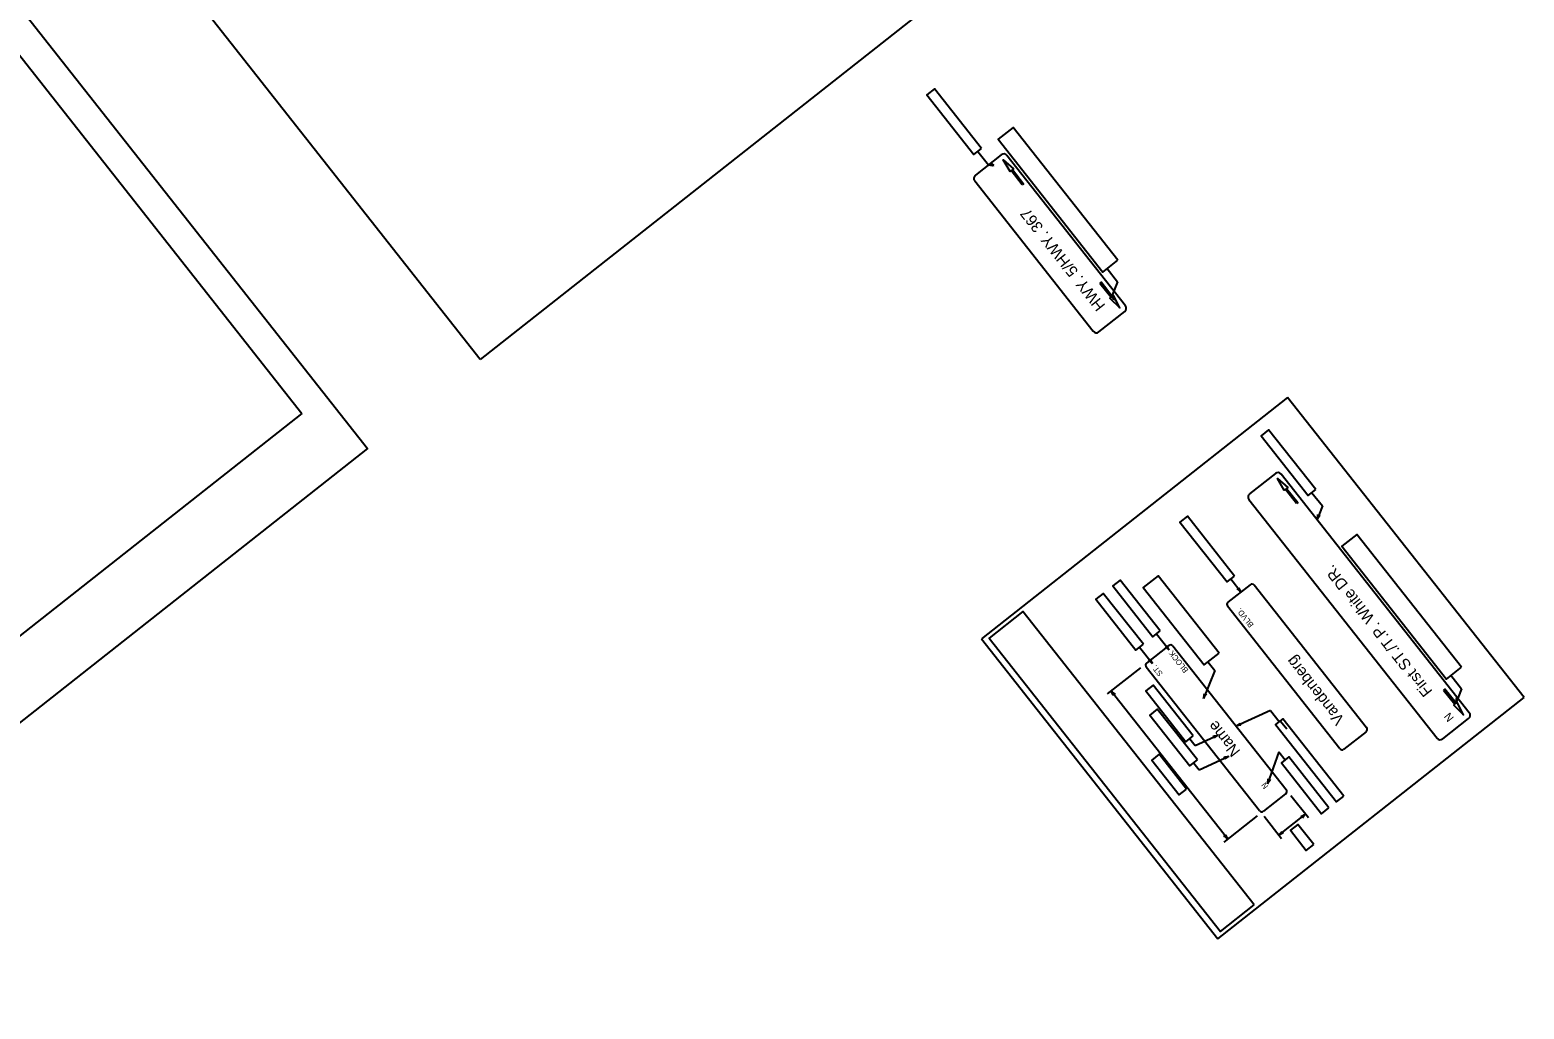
# Model space of a CAD drawing. Extents: x 671946 to 673995, y 1673066 to 1674936.
# Drawn here: x 672850 to 673939, y 1673066 to 1673780 of the extents above; entities that cross this region are included whole.
import ezdxf

# ---------------------------------------------------------------- set-up
doc = ezdxf.new("R2010")
doc.units = 0
for name, color, linetype in [('1', 7, 'Continuous'), ('Default', 7, 'Continuous'), ('G-ANNO-TTLB', 7, 'Continuous'), ('No Plot', 7, 'Continuous'), ('R_No Plot', 7, 'Continuous'), ('T_Drafting', 7, 'Continuous')]:
    doc.layers.add(name, color=color, linetype=linetype)

msp = doc.modelspace()

# ---------------------------------------------------------------- linework, layer by layer
at = {"layer": '1'}
for p, q in [((672460.5, 1674245.5), (673047.7, 1673500.6)), ((673047.7, 1673500.6), (672563.7, 1673119))]:
    msp.add_line(p, q, dxfattribs=at)
at = {"layer": 'Default'}
for points in [[(673543.2, 1673693.5), (673508.8, 1673737.1), (673503.4, 1673732.8), (673537.7, 1673689.2)], [(673642.5, 1673612.2), (673566.2, 1673709), (673555.3, 1673700.4), (673631.6, 1673603.6)], [(673786.8, 1673445), (673752.4, 1673488.6), (673746.9, 1673484.3), (673781.3, 1673440.7)], [(673727.5, 1673382), (673693.2, 1673425.7), (673687.7, 1673421.4), (673722.1, 1673377.8)], [(673893, 1673315.6), (673816.7, 1673412.4), (673805.8, 1673403.8), (673882.1, 1673307)], [(673716.4, 1673325.9), (673671.9, 1673382.3), (673661, 1673373.7), (673705.5, 1673317.3)], [(673673.5, 1673342), (673644.3, 1673379.1), (673638.8, 1673374.8), (673668.1, 1673337.7)], [(673661.2, 1673332.3), (673631.9, 1673369.4), (673626.5, 1673365.1), (673655.7, 1673328)], [(673697.5, 1673265.5), (673668.3, 1673302.6), (673662.9, 1673298.3), (673692.1, 1673261.2)], [(673700.5, 1673248), (673671.3, 1673285), (673665.8, 1673280.7), (673695.1, 1673243.7)], [(673807.3, 1673221.7), (673762.8, 1673278.1), (673757.4, 1673273.8), (673801.9, 1673217.4)], [(673692.6, 1673226.8), (673672.6, 1673252.2), (673667.2, 1673247.9), (673687.2, 1673222.5)], [(673796.4, 1673213.1), (673767.2, 1673250.2), (673761.7, 1673245.9), (673791, 1673208.8)], [(673785.4, 1673186.4), (673773.8, 1673201.1), (673768.3, 1673196.8), (673779.9, 1673182.1)]]:
    msp.add_lwpolyline(points, close=True, dxfattribs=at)
at = {"layer": 'G-ANNO-TTLB'}
msp.add_lwpolyline([(673177.8, 1673539.8), (672546.3, 1674340.9), (673064.6, 1674749.5), (673696.1, 1673948.5)], close=True, dxfattribs=at)
at = {"layer": 'No Plot'}
msp.add_lwpolyline([(673741.9, 1673142.5), (673573.4, 1673356.2), (673548.8, 1673336.8), (673717.3, 1673123.1)], close=True, dxfattribs=at)
at = {"layer": 'R_No Plot'}
msp.add_lwpolyline([(672577.3, 1673066.5), (671945.8, 1673867.5), (672464.1, 1674276.1), (673095.6, 1673475.1)], close=True, dxfattribs=at)
at = {"layer": 'T_Drafting'}
for p, q in [((673557.6, 1673689), (673538.7, 1673674.1)), ((673540.5, 1673691.3), (673548.2, 1673681.6)), ((673648.1, 1673579), (673561.7, 1673688.6)), ((673538.2, 1673670), (673624.6, 1673560.4)), ((673634.7, 1673606.2), (673642.4, 1673596.5)), ((673642.4, 1673596.5), (673638.4, 1673586.6)), ((673628.7, 1673559.9), (673647.6, 1673574.9)), ((673766.2, 1673512.2), (673543.1, 1673336.3)), ((673938.6, 1673293.5), (673766.2, 1673512.2)), ((673757.5, 1673456.8), (673738.5, 1673441.9)), ((673898.7, 1673282.4), (673761.6, 1673456.3)), ((673738.1, 1673437.8), (673875.2, 1673263.9)), ((673784, 1673442.8), (673791.7, 1673433.1)), ((673791.7, 1673433.1), (673787.7, 1673423.2)), ((673739, 1673375.7), (673722.8, 1673363)), ((673724.8, 1673379.9), (673732.3, 1673370.4)), ((673823.8, 1673271.5), (673741.9, 1673375.4)), ((673804.3, 1673256.2), (673722.5, 1673360.1)), ((673670.8, 1673339.9), (673680, 1673328.2)), ((673543.1, 1673336.3), (673715.5, 1673117.6)), ((673658.4, 1673330.1), (673667.7, 1673318.4)), ((673679.7, 1673331.4), (673663.5, 1673318.6)), ((673765.2, 1673226.3), (673682.6, 1673331)), ((673745.8, 1673211), (673663.2, 1673315.7)), ((673708.4, 1673319.4), (673713.3, 1673313.2)), ((673634.9, 1673296.1), (673659.2, 1673315.2)), ((673713.3, 1673313.2), (673705, 1673292.9)), ((673885.3, 1673309.7), (673893, 1673299.9)), ((673722.7, 1673190.2), (673637.6, 1673298.2)), ((673893, 1673299.9), (673889, 1673290)), ((673715.5, 1673117.6), (673938.6, 1673293.5)), ((673753.8, 1673284), (673728.7, 1673272.6)), ((673753.8, 1673284), (673760.1, 1673276)), ((673761.1, 1673276.4), (673765.7, 1673270.6)), ((673879.3, 1673263.4), (673898.2, 1673278.3)), ((673695, 1673263.5), (673698.8, 1673258.6)), ((673698.8, 1673258.6), (673715.5, 1673266.2)), ((673823.4, 1673268.6), (673807.2, 1673255.9)), ((673701.7, 1673240.9), (673723.4, 1673250.8)), ((673759.9, 1673253.9), (673751.7, 1673230.6)), ((673759.9, 1673253.9), (673764.5, 1673248)), ((673697.8, 1673245.8), (673701.7, 1673240.9)), ((673764.8, 1673223.4), (673748.7, 1673210.6)), ((673781.4, 1673205.8), (673768.6, 1673222)), ((673720, 1673188.1), (673744.3, 1673207.2)), ((673759.8, 1673193.2), (673779.2, 1673208.5)), ((673761.9, 1673190.5), (673749.2, 1673206.7))]:
    msp.add_line(p, q, dxfattribs=at)
for points in [[(673572.9, 1673667.2), (673564.8, 1673677.5), (673564, 1673676.8), (673558.9, 1673685.4), (673566.5, 1673678.8), (673565.7, 1673678.2), (673573.8, 1673667.9)], [(673629.5, 1673595.5), (673637.6, 1673585.2), (673636.8, 1673584.5), (673643.9, 1673577.6), (673639.3, 1673586.5), (673638.5, 1673585.8), (673630.3, 1673596.1)], [(673772.8, 1673434.9), (673764.7, 1673445.2), (673763.8, 1673444.6), (673758.8, 1673453.1), (673766.4, 1673446.6), (673765.5, 1673445.9), (673773.7, 1673435.6)], [(673880, 1673298.9), (673888.2, 1673288.6), (673887.3, 1673287.9), (673894.5, 1673281), (673889.9, 1673290), (673889, 1673289.3), (673880.9, 1673299.6)]]:
    msp.add_lwpolyline(points, close=True, dxfattribs=at)
for centre, radius, start, end in [((673559.4, 1673686.7), 2.92, 38.2505, 128.2505), ((673544, 1673708.1), 26.9, 278.933, 286.6711), ((673544.3, 1673655), 26.9, 73.9782, 81.7163), ((673553, 1673681.6), 1.49, 148.4773, 212.172), ((673540.5, 1673671.8), 2.92, 128.2505, 218.2505), ((673659.6, 1673603.1), 26.9, 217.9568, 225.6949), ((673613.3, 1673577), 26.9, 13.002, 20.7402), ((673640.8, 1673582.4), 1.49, 87.5012, 151.1958), ((673645.8, 1673577.2), 2.92, 308.2505, 38.2505), ((673626.9, 1673562.2), 2.92, 218.2505, 308.2505), ((673759.3, 1673454.5), 2.92, 38.2505, 128.2505), ((673740.4, 1673439.6), 2.92, 128.2505, 218.2505), ((673761.5, 1673429), 26.9, 347.5437, 355.2818), ((673811.1, 1673409.9), 26.9, 142.589, 150.3271), ((673789.4, 1673427.7), 1.49, 217.0881, 280.7827), ((673729.2, 1673374.2), 1.49, 277.4031, 341.0977), ((673714.2, 1673350.5), 26.9, 47.8587, 55.5968), ((673755.4, 1673384.1), 26.9, 202.904, 210.6421), ((673740.3, 1673374.1), 2.06, 38.2505, 128.2505), ((673724.1, 1673361.3), 2.06, 128.2505, 218.2505), ((673677, 1673331.9), 1.49, 277.4031, 341.0977), ((673662, 1673308.2), 26.9, 47.8587, 55.5968), ((673703.1, 1673341.9), 26.9, 202.904, 210.6421), ((673681, 1673329.8), 2.06, 38.2505, 128.2505), ((673664.8, 1673317), 2.06, 128.2505, 218.2505), ((673664.6, 1673322.2), 1.49, 277.4031, 341.0977), ((673649.6, 1673298.5), 26.9, 47.8587, 55.5968), ((673690.8, 1673332.2), 26.9, 202.904, 210.6421), ((673655.7, 1673318.1), 26.9, 227.8587, 235.5968), ((673614.5, 1673284.5), 26.9, 22.904, 30.6421), ((673640.7, 1673294.5), 1.49, 97.4031, 161.0977), ((673678.8, 1673298.7), 26.9, 347.5437, 355.2818), ((673728.4, 1673279.6), 26.9, 142.589, 150.3271), ((673706.8, 1673297.4), 1.49, 217.0881, 280.7827), ((673862.7, 1673295.8), 26.9, 347.5437, 355.2818), ((673912.3, 1673276.7), 26.9, 142.589, 150.3271), ((673890.7, 1673294.5), 1.49, 217.0881, 280.7827), ((673713.6, 1673294.8), 26.9, 304.1749, 311.913), ((673736.5, 1673246.9), 26.9, 99.2202, 106.9583), ((673733, 1673274.7), 1.49, 173.7193, 237.4139), ((673896.4, 1673280.6), 2.92, 308.2505, 38.2505), ((673707.7, 1673291.9), 26.9, 279.2202, 286.9583), ((673711.2, 1673264.1), 1.49, 353.7193, 57.4139), ((673730.6, 1673243.9), 26.9, 124.1749, 131.913), ((673822.2, 1673270.3), 2.06, 308.2505, 38.2505), ((673877.4, 1673265.7), 2.92, 218.2505, 308.2505), ((673715.6, 1673276.6), 26.9, 279.2202, 286.9583), ((673738.5, 1673228.6), 26.9, 124.1749, 131.913), ((673806, 1673257.5), 2.06, 218.2505, 308.2505), ((673719.1, 1673248.8), 1.49, 353.7193, 57.4139), ((673725.2, 1673235.1), 26.9, 350.3639, 358.102), ((673775.7, 1673218.4), 26.9, 145.4092, 153.1473), ((673753.2, 1673235.1), 1.49, 219.9083, 283.6029), ((673763.6, 1673225), 2.06, 308.2505, 38.2505), ((673747.4, 1673212.3), 2.06, 218.2505, 308.2505), ((673765.5, 1673231.6), 26.9, 292.904, 300.6421), ((673775.5, 1673205.5), 1.49, 7.4031, 71.0977), ((673799.2, 1673190.4), 26.9, 137.8587, 145.5968), ((673739.9, 1673211.2), 26.9, 317.8587, 325.5968), ((673763.5, 1673196.2), 1.49, 187.4031, 251.0977), ((673719.7, 1673193.9), 1.49, 277.4031, 341.0977), ((673704.7, 1673170.3), 26.9, 47.8587, 55.5968), ((673745.9, 1673203.9), 26.9, 202.904, 210.6421), ((673773.5, 1673170), 26.9, 112.904, 120.6421)]:
    msp.add_arc(centre, radius, start, end, dxfattribs=at)

# ---------------------------------------------------------------- texts
for s, height, p in [('HWY. 5/HWY. 367', 8.249, (673633.8, 1673579.2)), ('First ST./T.P. White DR.', 8.249, (673872.2, 1673298.1)), ('BLVD.', 4.12, (673741.8, 1673346.6)), ('BLOCK', 4.12, (673694.2, 1673313.5)), ('ST.', 4.12, (673675.6, 1673311)), ('Vandenberg', 8.25, (673808.2, 1673277.5)), ('Name', 8.25, (673732.2, 1673254.4)), ('N', 5.83, (673887.8, 1673278.7)), ('N', 4.12, (673752.4, 1673228.9))]:
    msp.add_text(s, height=height, rotation=128.2505, dxfattribs=at).set_placement(p)

doc.saveas('drawing.dxf')
